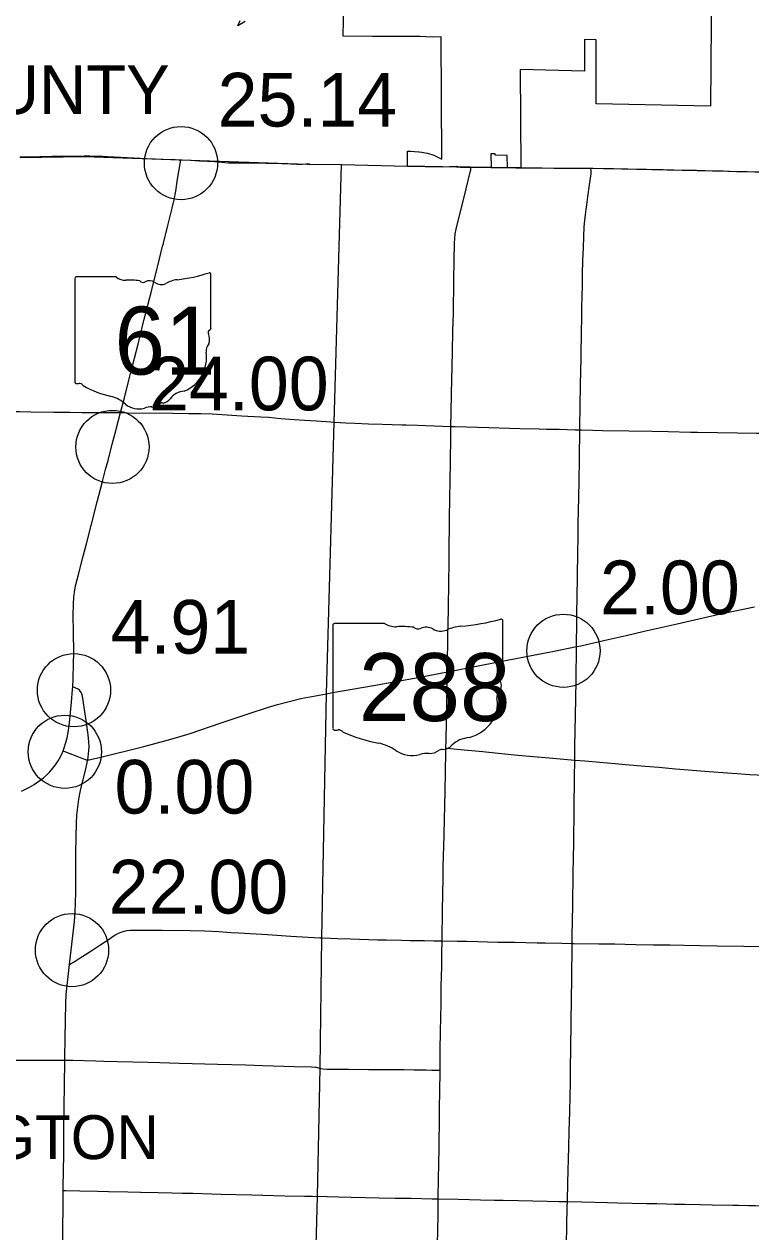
# Model space of a CAD drawing. Extents: x 1813937 to 1948437, y 826606 to 1022856.
# Drawn here: x 1878388 to 1893278, y 966228 to 990989 of the extents above; entities that cross this region are included whole.
import ezdxf

# ---------------------------------------------------------------- set-up
doc = ezdxf.new("R2010")
doc.units = 0
for name, color, linetype in [('Default', 7, 'Continuous'), ('GM_X_Adjacent_County_Text', 7, 'Continuous'), ('GM_X_Corporation', 7, 'Continuous'), ('GM_X_County', 7, 'Continuous'), ('GM_X_County_Road', 7, 'Continuous'), ('GM_X_State_Route', 7, 'Continuous'), ('GM_X_State_Shield', 7, 'Continuous'), ('GM_X_Township', 7, 'Continuous'), ('GM_X_Township_Road', 7, 'Continuous'), ('GM_X_Township_Text', 7, 'Continuous')]:
    doc.layers.add(name, color=color, linetype=linetype)

msp = doc.modelspace()

# ---------------------------------------------------------------- linework, layer by layer
at = {"layer": 'Default'}
for centre in [(1881602, 988140), (1880197, 982321), (1889438, 978141), (1879408, 977333), (1879221, 976070), (1879369, 972005)]:
    msp.add_circle(centre, 750, dxfattribs=at)
at = {"layer": 'GM_X_Corporation'}
for points in [[(1892482, 992695), (1892450, 989306), (1890112, 989352), (1890108, 990670), (1889867, 990675), (1889871, 990063), (1889870, 990022), (1888549, 990056), (1888567, 988043), (1888291, 988047), (1888288, 988299), (1888037, 988302), (1888037, 988329), (1887952, 988330), (1887954, 988052), (1887533, 988056), (1887406, 988055), (1887332, 988057), (1887307, 988059), (1887249, 988060), (1886959, 988065), (1886245, 988079), (1886244, 988388), (1886308, 988385), (1886388, 988378), (1886474, 988371), (1886485, 988370), (1886537, 988364), (1886602, 988354), (1886653, 988345), (1886695, 988333), (1886740, 988318), (1886763, 988309), (1886785, 988300), (1886839, 988275), (1886893, 988250), (1886947, 988223), (1886931, 990731), (1886747, 990725), (1886498, 990734), (1885527, 990737), (1884925, 990744), (1884954, 992065)], [(1882916, 991043), (1882769, 990956), (1882816, 991062)]]:
    msp.add_lwpolyline(points, dxfattribs=at)
at = {"layer": 'GM_X_County'}
msp.add_lwpolyline([(1878309, 988257), (1879625, 988278), (1881591, 988207), (1884186, 988121), (1884889, 988110), (1886245, 988079), (1886959, 988065), (1887247, 988078), (1887277, 988068), (1887305, 988061), (1887332, 988057), (1887406, 988055), (1887534, 988056), (1887954, 988052), (1888291, 988047), (1888567, 988043), (1888789, 988041), (1889241, 988035), (1890006, 988038), (1892176, 987990), (1895013, 987926)], dxfattribs=at)
at = {"layer": 'GM_X_County_Road'}
for points in [[(1887133, 982742), (1887138, 983036), (1887145, 983413), (1887162, 984266), (1887174, 984709), (1887183, 985054), (1887195, 985743), (1887201, 986153), (1887205, 986497), (1887210, 986595), (1887222, 986692), (1887240, 986789), (1887318, 987091), (1887384, 987361), (1887446, 987616), (1887528, 987951), (1887538, 988001), (1887539, 988021), (1887538, 988035), (1887537, 988057)], [(1887251, 988079), (1887281, 988069), (1887308, 988062), (1887336, 988058), (1887410, 988056), (1887537, 988057)], [(1889775, 982670), (1889775, 982731), (1889783, 983158), (1889789, 983601), (1889799, 984143), (1889810, 984733), (1889814, 984914), (1889818, 985176), (1889823, 985422), (1889829, 985618), (1889831, 985749), (1889832, 985864), (1889838, 986143), (1889847, 986405), (1889854, 986635), (1889864, 986832), (1889874, 986963), (1889889, 987077), (1889905, 987190), (1889919, 987287), (1889937, 987450), (1889971, 987693), (1890004, 987921), (1890008, 987985), (1890006, 987998), (1890002, 988008), (1889995, 988022), (1889986, 988034)], [(1874277, 983063), (1874390, 983063), (1874964, 983063), (1875374, 983063), (1875702, 983061), (1876063, 983060), (1876572, 983057), (1877195, 983051), (1877555, 983049), (1877785, 983048), (1877916, 983047), (1878293, 983044), (1878523, 983041), (1878998, 983036), (1879326, 983034), (1879572, 983030), (1879834, 983026), (1880113, 983025), (1880309, 983024), (1880352, 983024), (1880363, 983024)], [(1887061, 977710), (1887063, 977813), (1887072, 978453), (1887082, 978978), (1887085, 979224), (1887088, 979339), (1887092, 979534), (1887093, 979696), (1887094, 979792), (1887097, 980100), (1887106, 980871), (1887117, 981642), (1887121, 982003), (1887131, 982544), (1887133, 982724), (1887133, 982742)], [(1889705, 978226), (1889707, 978335), (1889710, 978646), (1889714, 978942), (1889719, 979221), (1889736, 980140), (1889740, 980484), (1889743, 980763), (1889745, 980993), (1889754, 981320), (1889760, 981599), (1889766, 982092), (1889775, 982670)], [(1889775, 982670), (1889810, 982669), (1890039, 982664), (1890236, 982660), (1890777, 982650), (1891253, 982641), (1891581, 982635), (1892040, 982626), (1892187, 982623), (1892597, 982617), (1893007, 982610), (1893384, 982604), (1893613, 982600), (1893744, 982597), (1894021, 982589), (1894087, 982587), (1894268, 982583), (1894530, 982582), (1894793, 982578), (1894891, 982575), (1894907, 982574), (1894932, 982573)], [(1889671, 975899), (1889674, 976185), (1889686, 976808), (1889696, 977530), (1889705, 978226)], [(1887031, 976151), (1887034, 976304), (1887056, 977420), (1887061, 977710)], [(1886950, 972193), (1886951, 972319), (1886959, 972729), (1886962, 972893), (1886966, 973073), (1886969, 973221), (1886972, 973418), (1886977, 973713), (1886991, 974352), (1886999, 974713), (1887006, 974943), (1887021, 975632), (1887030, 976091), (1887031, 976151)], [(1889618, 972143), (1889620, 972296), (1889629, 972919), (1889640, 973592), (1889644, 973887), (1889648, 974199), (1889658, 974905), (1889667, 975545), (1889671, 975899)], [(1889671, 975899), (1889680, 975899), (1889875, 975882), (1890185, 975857), (1890495, 975829), (1890708, 975811), (1891116, 975777), (1891394, 975752), (1891737, 975724), (1892424, 975669), (1892800, 975641), (1892996, 975625), (1893170, 975612)], [(1893170, 975612), (1893257, 975605), (1893405, 975595), (1893584, 975588), (1894108, 975560), (1894780, 975521), (1894867, 975515)], [(1886911, 969542), (1886913, 969744), (1886915, 969957), (1886920, 970335), (1886930, 970908), (1886936, 971269), (1886939, 971466), (1886943, 971663), (1886946, 971942), (1886950, 972193)], [(1889520, 966850), (1889528, 967242), (1889547, 967964), (1889557, 968292), (1889566, 968686), (1889573, 969014), (1889580, 969276), (1889586, 969572), (1889592, 969998), (1889606, 971016), (1889611, 971393), (1889618, 972143)], [(1874573, 969761), (1874584, 969760), (1874629, 969754), (1874713, 969754), (1874860, 969754), (1875057, 969756), (1875204, 969756), (1875417, 969757), (1875974, 969755), (1876187, 969755), (1876465, 969756), (1876645, 969755), (1876793, 969753), (1877038, 969751), (1877186, 969750), (1877448, 969749), (1877890, 969747), (1878250, 969746), (1878610, 969747), (1879069, 969749), (1879220, 969750)], [(1886873, 966904), (1886872, 966954), (1886878, 967295), (1886886, 967639), (1886890, 967918), (1886893, 968164), (1886896, 968377), (1886901, 968836), (1886904, 969033), (1886904, 969076), (1886906, 969218), (1886906, 969232), (1886906, 969248), (1886906, 969260), (1886906, 969267), (1886906, 969278), (1886908, 969300), (1886910, 969334), (1886910, 969515), (1886911, 969542)], [(1879189, 967078), (1879234, 967077), (1879529, 967070), (1879890, 967062), (1880119, 967057), (1880513, 967048), (1880775, 967042), (1881136, 967034), (1881415, 967028), (1881628, 967022), (1881841, 967018), (1882038, 967012), (1882415, 967001), (1883055, 966984), (1883728, 966969), (1884138, 966960), (1884299, 966957)], [(1884299, 966957), (1884597, 966951), (1884827, 966945), (1885089, 966939), (1885663, 966928), (1885991, 966922), (1886320, 966917), (1886746, 966906), (1886873, 966904)], [(1886873, 966904), (1887281, 966896), (1887512, 966890), (1887742, 966885), (1888021, 966879), (1888202, 966876), (1888514, 966869), (1889105, 966856), (1889352, 966852), (1889499, 966850), (1889520, 966850)], [(1889424, 961538), (1889434, 962041), (1889441, 962402), (1889451, 963025), (1889459, 963534), (1889476, 964387), (1889485, 964945), (1889494, 965470), (1889503, 965962), (1889509, 966356), (1889517, 966733), (1889520, 966850)], [(1889520, 966850), (1889815, 966844), (1890339, 966831), (1890552, 966826), (1891142, 966812), (1891355, 966807), (1891551, 966803), (1891715, 966799), (1891830, 966797), (1891928, 966795), (1892240, 966789), (1892486, 966783), (1892912, 966776), (1893027, 966774), (1893240, 966769), (1893371, 966766), (1893551, 966761), (1893830, 966755), (1893978, 966753), (1894174, 966750), (1894502, 966742), (1894748, 966737)]]:
    msp.add_lwpolyline(points, dxfattribs=at)
at = {"layer": 'GM_X_State_Route'}
for points in [[(1881240, 986494), (1881241, 986497), (1881334, 986863), (1881422, 987213), (1881461, 987389), (1881493, 987567), (1881531, 987810), (1881599, 988208)], [(1880540, 983720), (1880575, 983857), (1880721, 984429), (1880849, 984938), (1881003, 985542), (1881164, 986179), (1881226, 986434), (1881240, 986494)], [(1880266, 982653), (1880282, 982713), (1880363, 983024), (1880434, 983300), (1880540, 983720)], [(1879887, 981197), (1879988, 981586), (1880058, 981856), (1880107, 982046), (1880194, 982380), (1880234, 982531), (1880266, 982653)], [(1879384, 977403), (1879392, 977559), (1879402, 977887), (1879403, 978084), (1879397, 978543), (1879395, 978855), (1879397, 979101), (1879405, 979231), (1879419, 979345), (1879443, 979474), (1879492, 979681), (1879595, 980078), (1879670, 980363), (1879762, 980712), (1879887, 981197)], [(1879690, 975904), (1879702, 975904), (1879719, 975906), (1879774, 975917), (1879933, 975955), (1880235, 976031), (1880538, 976106), (1880840, 976181), (1881269, 976294), (1881537, 976369), (1881787, 976449), (1882425, 976664), (1883000, 976858), (1883374, 976981), (1883579, 977042), (1883817, 977105), (1884057, 977161), (1884282, 977206), (1884583, 977260), (1884670, 977276), (1885543, 977430), (1886463, 977595), (1887061, 977710), (1887172, 977732), (1888107, 977913), (1888960, 978079), (1889250, 978135), (1889705, 978226), (1889797, 978245), (1890293, 978359), (1890725, 978458), (1891092, 978544), (1891460, 978628), (1891765, 978696), (1892388, 978840), (1892693, 978906), (1893352, 979041)], [(1878334, 975264), (1878495, 975346), (1878594, 975403), (1878690, 975467), (1878782, 975537), (1878844, 975591), (1878914, 975661), (1878978, 975735), (1879028, 975801), (1879082, 975883), (1879140, 975983), (1879175, 976058), (1879188, 976091), (1879211, 976150), (1879245, 976260), (1879269, 976356), (1879290, 976469), (1879316, 976664), (1879361, 977088), (1879380, 977349), (1879384, 977403)], [(1879690, 975904), (1879700, 975962), (1879709, 976031), (1879715, 976095), (1879717, 976174), (1879714, 976272), (1879699, 976418), (1879657, 976711), (1879582, 977213), (1879570, 977260), (1879556, 977289), (1879538, 977315), (1879522, 977333), (1879503, 977347), (1879485, 977358), (1879462, 977370), (1879436, 977382), (1879384, 977403)], [(1879188, 976091), (1879235, 976073), (1879465, 975984), (1879572, 975942), (1879648, 975912), (1879662, 975908), (1879679, 975905), (1879690, 975904)], [(1879178, 965960), (1879189, 967078), (1879189, 967141), (1879198, 967813), (1879201, 968256), (1879207, 968813), (1879213, 969224), (1879220, 969750), (1879220, 969798), (1879229, 970208), (1879243, 970913), (1879252, 971093), (1879274, 971338), (1879317, 971710), (1879417, 972593), (1879434, 972789), (1879442, 972969), (1879446, 973198), (1879448, 973641), (1879449, 973985), (1879451, 974330), (1879458, 974608), (1879468, 974772), (1879485, 974935), (1879509, 975098), (1879544, 975275), (1879585, 975451), (1879647, 975689), (1879681, 975849), (1879690, 975904)]]:
    msp.add_lwpolyline(points, dxfattribs=at)
at = {"layer": 'GM_X_State_Shield'}
for p, q in [((1879429, 985769), (1879429, 983656)), ((1880272, 985805), (1879456, 985805)), ((1882213, 984752), (1882213, 985858)), ((1882213, 984753), (1882213, 984752)), ((1884716, 978665), (1884716, 976552)), ((1885769, 978701), (1884750, 978701)), ((1888196, 977648), (1888196, 978754)), ((1888196, 977648), (1888196, 977648))]:
    msp.add_line(p, q, dxfattribs=at)
for centre, radius, start, end in [((1879461, 985774), 32.3, 98.1301, 188.1301), ((1880466, 986051), 313, 231.6195, 271.1119), ((1880570, 984619), 1123, 80.4867, 94.9883), ((1880825, 985785), 90.3, 219.7921, 297.1024), ((1880957, 985540), 188, 54.4667, 119.1411), ((1881598, 985160), 594, 97.3462, 120.7689), ((1881222, 988687), 2953, 275.8445, 288.9065), ((1882182, 985862), 31, 351.8621, 97.738), ((1881199, 985875), 226, 233.8562, 294.8282), ((1882180, 984748), 33.2, 289.6038, 7.7341), ((1882206, 984671), 48, 107.944, 210.337), ((1881901, 984531), 288, 340.033, 23.6496), ((1881387, 984149), 739, 292.3089, 8.9858), ((1882324, 984290), 210, 136.8065, 186.9296), ((1879461, 983651), 32.5, 171.9584, 258.3066), ((1879466, 983867), 248, 267.339, 280.6039), ((1879517, 983534), 89.5, 29.7484, 93.2717), ((1880648, 985433), 2132, 240.4129, 257.1985), ((1880012, 982706), 667, 47.1842, 75.836), ((1881186, 983451), 239, 282.8732, 323.2771), ((1881698, 983062), 404, 94.4031, 142.5768), ((1880733, 983523), 423, 230.7004, 286.2918), ((1880978, 982793), 348, 85.6951, 111.2099), ((1881009, 983365), 226, 268.777, 315.5493), ((1881213, 983160), 63.5, 65.7517, 132.6484)]:
    msp.add_arc(centre, radius, start, end, dxfattribs=at)
for centre, major_axis, start_param, end_param in [((1886956, 981582), (3691, 0), 4.814394, 5.042369), ((1888157, 978758), (38.7, 0), 6.141152, 7.989035), ((1884755, 978669), (40.3, 0), 1.712693, 3.28349), ((1886012, 978947), (391, 0), 4.042523, 4.731795), ((1886141, 977515), (1404, 0), 1.404758, 1.657858), ((1886460, 978680), (113, 0), 3.836095, 5.185415), ((1886626, 978436), (235, 0), 0.950623, 2.079405), ((1886929, 978771), (282, 0), 4.081561, 5.145723), ((1887427, 978056), (743, 0), 1.699011, 2.107814), ((1888187, 977567), (60, 0), 1.883978, 3.671073), ((1888155, 977644), (41.5, 0), 5.05454, 6.418171), ((1888335, 977186), (262, 0), 2.387724, 3.262537), ((1887806, 977427), (360, 0), 5.934695, 6.695948), ((1887163, 977045), (923, 0), 5.101752, 6.440018), ((1884756, 976547), (40.7, 0), 3.00124, 4.508301), ((1884762, 976763), (310, 0), 4.665946, 4.897461), ((1884825, 976430), (112, 0), 0.519207, 1.627899), ((1886239, 978328), (2665, 0), 4.195997, 4.488961), ((1887552, 975958), (506, 0), 1.647645, 2.488434), ((1885444, 975602), (834, 0), 0.823519, 1.323587), ((1886346, 976419), (529, 0), 4.026481, 4.996735), ((1886690, 976261), (282, 0), 4.691044, 5.507374), ((1886945, 976056), (79.4, 0), 1.147584, 2.315152), ((1886912, 976347), (298, 0), 4.937069, 5.64225), ((1886652, 975689), (435, 0), 1.495662, 1.94098)]:
    msp.add_ellipse(centre, major_axis=major_axis, ratio=0.8, start_param=start_param, end_param=end_param, dxfattribs=at)
at = {"layer": 'GM_X_Township'}
msp.add_lwpolyline([(1884254, 961672), (1884396, 966955), (1884454, 969588), (1884489, 972257), (1884586, 977269), (1884741, 982824), (1884889, 988110)], dxfattribs=at)
at = {"layer": 'GM_X_Township_Road'}
for points in [[(1878301, 988267), (1878457, 988268), (1878956, 988279), (1879160, 988283), (1879620, 988289)], [(1879620, 988289), (1879732, 988288), (1879880, 988284), (1879995, 988279), (1880093, 988274), (1880765, 988244), (1880896, 988237), (1881073, 988227), (1881237, 988220), (1881481, 988211), (1881559, 988209), (1881599, 988208)], [(1881599, 988208), (1881624, 988207), (1881788, 988198), (1881810, 988197)], [(1881810, 988197), (1881886, 988194), (1881979, 988190)], [(1881979, 988190), (1882082, 988186), (1882145, 988183), (1882209, 988181), (1882291, 988175), (1882356, 988168), (1882437, 988157), (1882503, 988151), (1882572, 988146), (1882642, 988145)], [(1882642, 988145), (1882730, 988143), (1882928, 988145), (1883051, 988143), (1883208, 988144), (1883339, 988142), (1883421, 988141), (1883568, 988136), (1883667, 988132), (1883847, 988125), (1883856, 988125)], [(1883856, 988125), (1883978, 988121), (1884093, 988120), (1884159, 988122), (1884208, 988126), (1884236, 988129)], [(1887537, 988057), (1887640, 988058), (1887958, 988053)], [(1887958, 988053), (1888295, 988048)], [(1888295, 988048), (1888461, 988045), (1888570, 988043)], [(1888570, 988043), (1888592, 988043), (1888773, 988042), (1888793, 988042)], [(1888793, 988042), (1889002, 988040), (1889239, 988037)], [(1889239, 988037), (1889574, 988034), (1889784, 988034), (1889833, 988034), (1889931, 988034), (1889986, 988034)], [(1889986, 988034), (1890029, 988033), (1890044, 988033)], [(1890044, 988033), (1890260, 988031), (1890461, 988028), (1890755, 988021), (1891138, 988014), (1891484, 988007), (1891917, 987998), (1892166, 987992)], [(1892166, 987992), (1892524, 987983), (1892708, 987979), (1892840, 987974), (1892988, 987971), (1893202, 987965), (1893357, 987962), (1893587, 987958), (1893898, 987952), (1894357, 987943), (1894603, 987937), (1894784, 987932), (1895012, 987925)], [(1880363, 983024), (1880500, 983022), (1881436, 983011), (1881764, 983007), (1881829, 983009), (1881943, 983007), (1882009, 983004), (1882238, 982997), (1882336, 982991), (1882549, 982979), (1882844, 982959), (1883237, 982940), (1883401, 982928), (1883515, 982917), (1883645, 982901), (1883923, 982882), (1884133, 982869), (1884376, 982855), (1884671, 982833), (1884736, 982831)], [(1884736, 982831), (1884862, 982822), (1884867, 982822)], [(1884867, 982822), (1884978, 982815)], [(1884978, 982815), (1885165, 982807), (1885444, 982796), (1885723, 982788), (1886134, 982776), (1886216, 982773), (1886445, 982766), (1887133, 982742)], [(1887133, 982742), (1887217, 982739), (1887906, 982720), (1888546, 982700), (1888940, 982691), (1889088, 982686), (1889219, 982683), (1889350, 982682), (1889678, 982672), (1889775, 982670)], [(1887031, 976151), (1887055, 976148), (1887332, 976121), (1887789, 976075), (1888099, 976042), (1888507, 976004), (1889144, 975946), (1889671, 975899)], [(1879317, 971710), (1879353, 971731), (1879410, 971763), (1879534, 971844), (1879644, 971915), (1879837, 972039), (1879961, 972119), (1880153, 972245), (1880194, 972275), (1880249, 972311), (1880322, 972349), (1880396, 972381), (1880443, 972396), (1880491, 972407), (1880557, 972414), (1880671, 972415), (1880918, 972413), (1881032, 972413), (1881213, 972414), (1881787, 972410), (1882082, 972400), (1882377, 972383), (1882623, 972368), (1882786, 972357), (1883376, 972322), (1883851, 972292), (1884445, 972256)], [(1884445, 972256), (1884503, 972254)], [(1884503, 972254), (1884664, 972248), (1884811, 972242), (1885072, 972234), (1885628, 972218), (1885808, 972214), (1886119, 972207), (1886299, 972204), (1886593, 972199), (1886781, 972195), (1886950, 972193)], [(1886950, 972193), (1887259, 972190), (1887456, 972187), (1887685, 972180), (1887882, 972175), (1888095, 972170), (1888243, 972168), (1888440, 972166), (1888670, 972160), (1888899, 972156), (1889063, 972152), (1889408, 972146), (1889618, 972143)], [(1889618, 972143), (1889654, 972142), (1890163, 972136), (1890491, 972130), (1890917, 972121), (1891278, 972116), (1891623, 972111), (1891902, 972107), (1892591, 972095), (1893132, 972086), (1893584, 972080), (1893789, 972077), (1894018, 972071), (1894460, 972064), (1894558, 972062), (1894706, 972059), (1894818, 972056)], [(1879220, 969750), (1879267, 969749), (1879382, 969746), (1879858, 969736), (1880022, 969729), (1880301, 969721), (1880613, 969713), (1880925, 969704), (1881171, 969697), (1881565, 969686), (1881828, 969681), (1882353, 969669), (1882928, 969654), (1883273, 969641), (1883930, 969621), (1884275, 969611), (1884356, 969605), (1884372, 969602)], [(1884372, 969602), (1884443, 969583)], [(1884443, 969583), (1884461, 969578), (1884509, 969570), (1884591, 969566), (1885034, 969563), (1885444, 969558), (1885559, 969557), (1885755, 969557), (1885903, 969556), (1886165, 969554), (1886378, 969551), (1886624, 969549), (1886739, 969546), (1886870, 969542), (1886886, 969542), (1886911, 969542)], [(1886785, 961597), (1886785, 961626), (1886789, 961756), (1886793, 961953), (1886797, 962182), (1886807, 962674), (1886811, 962985), (1886819, 963460), (1886826, 963852), (1886829, 964033), (1886828, 964697), (1886831, 964812), (1886842, 964956), (1886848, 965186), (1886852, 965497), (1886857, 965710), (1886859, 965923), (1886866, 966316), (1886870, 966513), (1886873, 966709), (1886874, 966824), (1886873, 966904)]]:
    msp.add_lwpolyline(points, dxfattribs=at)

# ---------------------------------------------------------------- texts
at = {"layer": 'Default'}
for s, p in [('25.14', (1882352, 988890)), ('24.00', (1880947, 983071)), ('2.00', (1890188, 978891)), ('4.91', (1880158, 978083)), ('0.00', (1880240, 974804)), ('22.00', (1880119, 972755))]:
    msp.add_text(s, height=1100, dxfattribs=at).set_placement(p)
at = {"layer": 'GM_X_Adjacent_County_Text'}
msp.add_text('CRAWFORD COUNTY', height=1000, dxfattribs=at).set_placement((1867478, 989145))
at = {"layer": 'GM_X_State_Shield'}
for s, p in [('61', (1880239, 983805)), ('288', (1885247, 976701))]:
    msp.add_text(s, height=1392.2, dxfattribs=at).set_placement(p)
at = {"layer": 'GM_X_Township_Text'}
msp.add_text('WASHINGTON', height=900, rotation=0, dxfattribs=at).set_placement((1872858, 967719))

doc.saveas('drawing.dxf')
